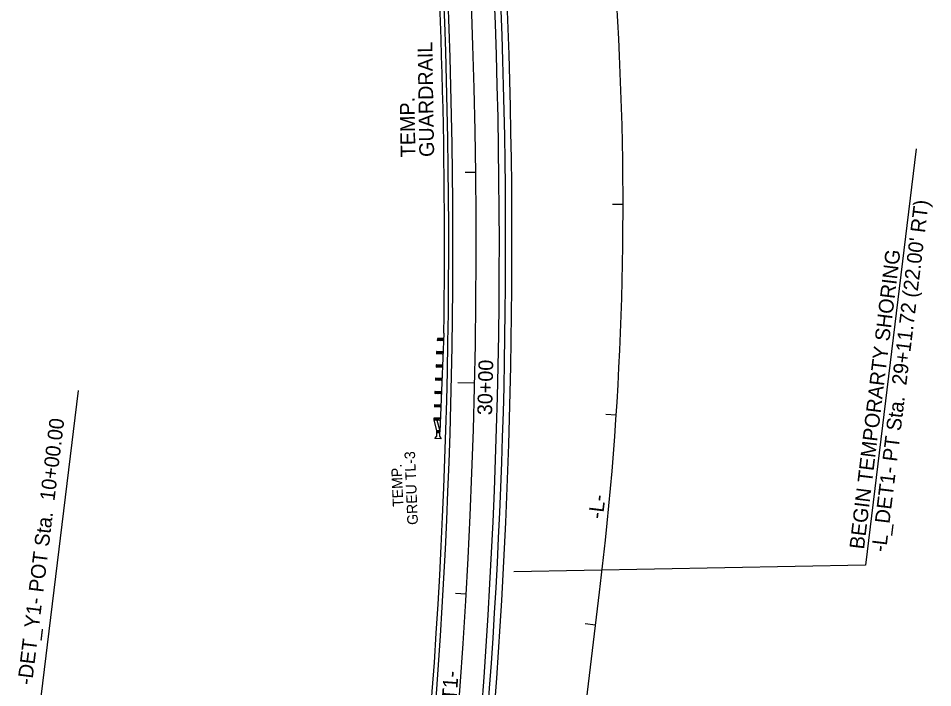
# Model space of a CAD drawing. Extents: x 473658 to 481584, y 489119 to 506230.
# Drawn here: x 481126.5 to 481560.3, y 491150.2 to 491467.6 of the extents above; entities that cross this region are included whole.
import ezdxf

# ---------------------------------------------------------------- set-up
doc = ezdxf.new("R2010")
doc.units = 0
for name, color, linetype in [('Prop Conc Barrier', 7, 'Continuous'), ('Prop EOT', 7, 'Continuous'), ('Prop Guardrail', 7, 'Continuous'), ('Prop Guardrail Anchor Unit CELL', 7, 'Continuous'), ('Prop Horizontal Alignment', 7, 'Continuous'), ('Prop Horizontal Alignment Direction Label', 7, 'Continuous'), ('Prop Horizontal Alignment Station Label', 7, 'Continuous'), ('Prop Horizontal Alignment Tick Label', 7, 'Continuous'), ('Prop Horizontal Alignment Tick Large', 7, 'Continuous'), ('Prop Horizontal Alignment Tick Small', 7, 'Continuous'), ('Prop Paved Shoulder', 7, 'Continuous'), ('Scratch_Level_0', 7, 'Continuous'), ('Sheet Profile Grid Major CELL', 7, 'Continuous')]:
    doc.layers.add(name, color=color, linetype=linetype)

msp = doc.modelspace()

# ---------------------------------------------------------------- linework, layer by layer
at = {"layer": 'Prop Conc Barrier'}
msp.add_arc((478448.2, 491360.34), 2909.5, 353.03651, 8.05328, dxfattribs=at)
at = {"layer": 'Prop EOT'}
for radius, end in [(2906, 11.67572), (2884, 10.48724)]:
    msp.add_arc((478448.7, 491360.28), radius, 353.03651, end, dxfattribs=at)
at = {"layer": 'Prop Guardrail'}
msp.add_arc((478448.7, 491360.28), 2880, 359.16561, 9.61015, dxfattribs=at)
at = {"layer": 'Prop Guardrail Anchor Unit CELL'}
for p, q in [((481325.29, 491315.85), (481325.24, 491314.85)), ((481325.24, 491314.85), (481326.78, 491315.78)), ((481328.28, 491315.72), (481325.29, 491315.85)), ((481326.74, 491314.78), (481325.29, 491315.85)), ((481328.39, 491318.26), (481326.4, 491271.55)), ((481326.78, 491315.78), (481326.74, 491314.78)), ((481326.74, 491314.78), (481328.28, 491315.72)), ((481326.78, 491315.78), (481328.24, 491314.72)), ((481328.28, 491315.72), (481328.24, 491314.72)), ((481328.24, 491314.72), (481325.24, 491314.85)), ((481328.24, 491314.72), (481326.74, 491314.78)), ((481324.96, 491309.55), (481324.92, 491308.55)), ((481324.92, 491308.55), (481326.49, 491309.49)), ((481327.97, 491308.42), (481324.92, 491308.55)), ((481328.01, 491309.42), (481324.96, 491309.55)), ((481326.45, 491308.49), (481324.96, 491309.55)), ((481326.49, 491309.49), (481326.45, 491308.49)), ((481328.01, 491309.42), (481326.45, 491308.49)), ((481326.49, 491309.49), (481327.97, 491308.42)), ((481324.7, 491303.26), (481324.66, 491302.26)), ((481324.66, 491302.26), (481326.22, 491303.19)), ((481327.7, 491302.13), (481324.66, 491302.26)), ((481327.74, 491303.13), (481324.7, 491303.26)), ((481326.18, 491302.19), (481324.7, 491303.26)), ((481326.22, 491303.19), (481326.18, 491302.19)), ((481327.74, 491303.13), (481326.18, 491302.19)), ((481326.22, 491303.19), (481327.7, 491302.13)), ((481324.44, 491296.96), (481324.4, 491295.96)), ((481324.4, 491295.96), (481325.96, 491296.9)), ((481327.43, 491295.83), (481324.4, 491295.96)), ((481327.48, 491296.83), (481324.44, 491296.96)), ((481325.92, 491295.9), (481324.44, 491296.96)), ((481325.96, 491296.9), (481325.92, 491295.9)), ((481327.48, 491296.83), (481325.92, 491295.9)), ((481325.96, 491296.9), (481327.43, 491295.83)), ((481327.48, 491296.83), (481327.43, 491295.83)), ((481324.07, 491290.67), (481324.03, 491289.67)), ((481324.03, 491289.67), (481325.64, 491290.6)), ((481327.16, 491289.54), (481324.03, 491289.67)), ((481327.21, 491290.54), (481324.07, 491290.67)), ((481325.6, 491289.6), (481324.07, 491290.67)), ((481325.64, 491290.6), (481325.6, 491289.6)), ((481327.21, 491290.54), (481325.6, 491289.6)), ((481325.64, 491290.6), (481327.16, 491289.54)), ((481323.94, 491284.37), (481323.9, 491283.37)), ((481323.9, 491283.37), (481325.44, 491284.31)), ((481326.9, 491283.24), (481323.9, 491283.37)), ((481326.94, 491284.24), (481323.94, 491284.37)), ((481325.4, 491283.31), (481323.94, 491284.37)), ((481325.44, 491284.31), (481325.4, 491283.31)), ((481326.94, 491284.24), (481325.4, 491283.31)), ((481325.44, 491284.31), (481326.9, 491283.24)), ((481323.61, 491278.08), (481323.57, 491277.08)), ((481323.57, 491277.08), (481325.14, 491278.01)), ((481326.63, 491276.95), (481323.57, 491277.08)), ((481323.57, 491277.08), (481324.92, 491272.11)), ((481326.67, 491277.95), (481323.61, 491278.08)), ((481325.1, 491277.01), (481323.61, 491278.08)), ((481325.14, 491278.01), (481325.1, 491277.01)), ((481326.67, 491277.95), (481325.1, 491277.01)), ((481325.1, 491277.01), (481326.42, 491272.05)), ((481325.14, 491278.01), (481326.63, 491276.95)), ((481324.92, 491272.11), (481324.88, 491271.11)), ((481324.88, 491271.11), (481326.42, 491272.05)), ((481324.92, 491272.11), (481324.9, 491271.61)), ((481326.42, 491272.05), (481324.92, 491272.11)), ((481326.37, 491271.05), (481324.92, 491272.11)), ((481325.05, 491269.51), (481325.1, 491271.55)), ((481325.1, 491271.55), (481325.71, 491271.54)), ((481325.71, 491271.54), (481326.32, 491271.52)), ((481324.16, 491268.35), (481325.05, 491269.51)), ((481327.1, 491268.28), (481324.16, 491268.35)), ((481326.37, 491271.05), (481324.88, 491271.11)), ((481326.32, 491271.52), (481326.27, 491269.47)), ((481326.27, 491269.47), (481327.1, 491268.28))]:
    msp.add_line(p, q, dxfattribs=at)
at = {"layer": 'Prop Horizontal Alignment'}
msp.add_line((481200.24, 489541.46), (481402.27, 491195.58), dxfattribs=at)
for centre, radius, end in [((478448.7, 491360.28), 2895, 18.70399), ((479903.4, 491378.64), 1510, 12.98112)]:
    msp.add_arc(centre, radius, 353.03651, end, dxfattribs=at)
at = {"layer": 'Prop Horizontal Alignment Station Label'}
msp.add_line((481137.28, 491145.89), (481155.02, 491291.11), dxfattribs=at)
at = {"layer": 'Prop Horizontal Alignment Tick Large'}
msp.add_line((481342.95, 491294.52), (481334.96, 491294.71), dxfattribs=at)
at = {"layer": 'Prop Horizontal Alignment Tick Small'}
for p, q in [((481343.5, 491394.52), (481338.5, 491394.46)), ((481413.4, 491379.36), (481408.4, 491379.36)), ((481410.14, 491279.43), (481405.15, 491279.76)), ((481338.96, 491194.6), (481333.96, 491194.89)), ((481400.35, 491179.93), (481395.39, 491180.53))]:
    msp.add_line(p, q, dxfattribs=at)
at = {"layer": 'Prop Paved Shoulder'}
for centre, radius, start, end in [((478448.7, 491360.28), 2882, 353.03651, 10.60669), ((478448.2, 491360.26), 2912.5, 353.03855, 8.56944)]:
    msp.add_arc(centre, radius, start, end, dxfattribs=at)
at = {"layer": 'Scratch_Level_0'}
for p, q in [((481552.46, 491405.71), (481528.35, 491208.3)), ((481528.35, 491208.3), (481361.57, 491205.14))]:
    msp.add_line(p, q, dxfattribs=at)

# ---------------------------------------------------------------- texts
at = {"layer": 'Prop Guardrail Anchor Unit CELL'}
for s, p in [('GREU TL-3', (481316.11, 491227.51)), ('TEMP. ', (481309.19, 491236.04))]:
    msp.add_text(s, height=5, rotation=92.4042, dxfattribs=at).set_placement(p)
at = {"layer": 'Prop Horizontal Alignment Direction Label'}
for s, rotation, p in [('-L-', 83.0365, (481403.75, 491229.99)), ('-L_DET1-', 85.6162, (481332.31, 491117.49))]:
    msp.add_text(s, height=7, rotation=rotation, dxfattribs=at).set_placement(p)
at = {"layer": 'Prop Horizontal Alignment Station Label'}
msp.add_text('-DET_Y1- POT Sta.  10+00.00', height=7, rotation=83.0365, dxfattribs=at).set_placement((481132.97, 491151.27))
at = {"layer": 'Prop Horizontal Alignment Tick Label'}
msp.add_text('30+00', height=7, rotation=88.6984, dxfattribs=at).set_placement((481351.24, 491279.36))
at = {"layer": 'Scratch_Level_0'}
for s, p in [("-L_DET1- PT Sta.  29+11.72 (22.00' RT)", (481538.1, 491214.32)), ('BEGIN TEMPORARTY SHORING', (481527.67, 491215.6))]:
    msp.add_text(s, height=7, rotation=83.0365, dxfattribs=at).set_placement(p)
at = {"layer": 'Sheet Profile Grid Major CELL'}
for s, p in [('GUARDRAIL', (481323.78, 491401.91)), ('TEMP.', (481314.91, 491401.76))]:
    msp.add_text(s, height=7, rotation=90.9266, dxfattribs=at).set_placement(p)

doc.saveas('drawing.dxf')
